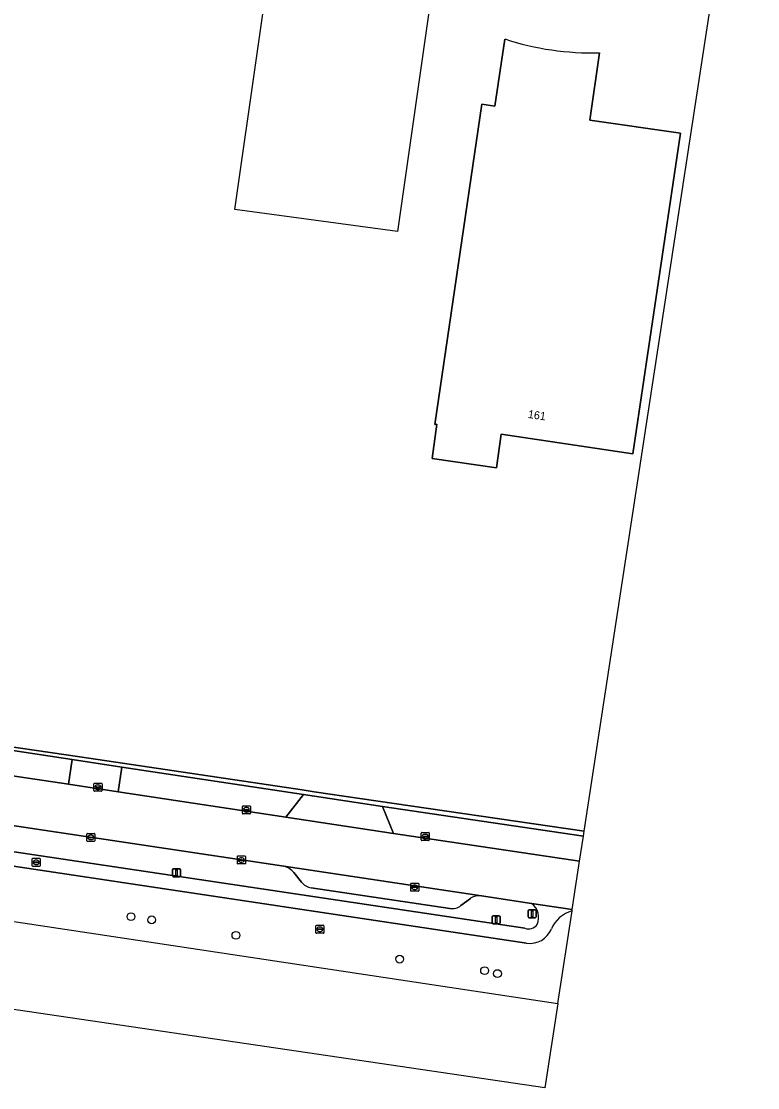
# Model space of a CAD drawing. Extents: x 163683 to 164494, y 382709 to 383872.
# Drawn here: x 164082.5 to 164174.5, y 382708.7 to 382841.9 of the extents above; entities that cross this region are included whole.
import ezdxf

# ---------------------------------------------------------------- set-up
doc = ezdxf.new("R2010")
doc.units = 0
for name, color, linetype in [('IMGEO_Berm_groen', 7, 'Continuous'), ('IMGEO_Boom', 7, 'Continuous'), ('IMGEO_Erf', 7, 'Continuous'), ('IMGEO_Fietspad_open', 7, 'Continuous'), ('IMGEO_Groenvoorziening', 7, 'Continuous'), ('IMGEO_Kolk', 7, 'Continuous'), ('IMGEO_Lichtmast', 7, 'Continuous'), ('IMGEO_Pand', 7, 'Continuous'), ('IMGEO_Pand_nummerreeks', 7, 'Continuous'), ('IMGEO_Pand_vergunning_verleend', 7, 'Continuous'), ('IMGEO_Parkeervlak_open', 7, 'Continuous'), ('IMGEO_Rijbaan_lokaal_open', 7, 'Continuous'), ('IMGEO_Rioolput', 7, 'Continuous'), ('IMGEO_Verkeersbordpaal', 7, 'Continuous'), ('IMGEO_Voetpad_open', 7, 'Continuous'), ('IMGEO_Waterloop', 7, 'Continuous')]:
    doc.layers.add(name, color=color, linetype=linetype)

msp = doc.modelspace()

# ---------------------------------------------------------------- linework, layer by layer
at = {"layer": 'IMGEO_Berm_groen'}
for points in [[(164025.95, 382749.73), (164025.49, 382746.53), (164145.37, 382728.61)], [(164115.25, 382736.34), (164025.95, 382749.73)], [(164117.47, 382734.35), (164116.5, 382735.56)], [(164136.02, 382731.08), (164118.7, 382733.66)], [(164138.61, 382732.34), (164137.39, 382731.46)], [(164146.24, 382731.7), (164139.98, 382732.64)]]:
    msp.add_lwpolyline(points, dxfattribs=at)
for centre, radius, start, end in [((164114.87, 382734.32), 2.05, 37.0321, 79.2448), ((164119.08, 382735.77), 2.15, 221.1897, 259.7116), ((164139.7, 382730.61), 2.05, 82.0143, 122.0036), ((164144.94, 382729.94), 2.18, 336.7961, 53.432), ((164136.34, 382732.62), 1.57, 258.5109, 312.0207), ((164145.85, 382729.86), 1.34, 249.196, 324.4701)]:
    msp.add_arc(centre, radius, start, end, dxfattribs=at)
at = {"layer": 'IMGEO_Boom'}
for centre in [(164096.16, 382730.05), (164098.75, 382729.65), (164109.28, 382727.72), (164129.75, 382724.75), (164140.36, 382723.31), (164141.97, 382722.94)]:
    msp.add_circle(centre, 0.489, dxfattribs=at)
at = {"layer": 'IMGEO_Erf'}
for points in [[(164076.6, 382751.95), (164089.76, 382750), (164117.54, 382745.89), (164119.07, 382745.66), (164124.77, 382744.83), (164152.81, 382740.72), (164172.2, 382867.23), (164171.72, 382867.3), (164174.49, 382886.26), (164165.52, 382887.66), (164165.46, 382887.29), (164147.17, 382890.23), (164146.96, 382890.27), (164142.09, 382891.05), (164141.8, 382889.15), (164141.95, 382889.13), (164141.39, 382885.06), (164138.4, 382885.49), (164138.99, 382889.54), (164139.16, 382889.51), (164139.68, 382892.92), (164090.55, 382900.02), (164089.55, 382900.17), (164080.01, 382901.54)], [(164154.71, 382837.95), (164153.53, 382829.54), (164164.83, 382827.91), (164158.9, 382787.87), (164142.42, 382790.3), (164141.84, 382786.12), (164133.8, 382787.27), (164134.41, 382791.55), (164134.14, 382791.52), (164140.03, 382831.52), (164141.65, 382831.28), (164142.88, 382839.68)]]:
    msp.add_lwpolyline(points, dxfattribs=at)
msp.add_arc((164153.84, 382873.25), 35.31, 251.9184, 271.4148, dxfattribs=at)
at = {"layer": 'IMGEO_Fietspad_open'}
for points in [[(164145.37, 382728.61), (164025.49, 382746.53), (164025.95, 382749.73), (164024.22, 382749.98), (164023.68, 382746.79), (163989.35, 382751.87), (163943.93, 382758.59), (163798.25, 382780.16), (163792.5, 382781.01), (163764.15, 382785.23), (163700.86, 382794.64), (163698.7, 382794.97), (163698.46, 382793.12), (163700.77, 382792.77), (163796.75, 382778.55), (163938.7, 382757.53), (163989.01, 382750.08), (164063.39, 382739.07), (164145.61, 382726.74)], [(164151.31, 382730.94), (164146.24, 382731.7)], [(164151.29, 382730.77), (164151.31, 382730.94)]]:
    msp.add_lwpolyline(points, dxfattribs=at)
for centre, radius, start, end in [((164144.94, 382729.94), 2.18, 336.7961, 53.432), ((164152.36, 382726.95), 3.97, 105.708, 156.7954), ((164145.85, 382729.86), 1.34, 249.196, 324.4701), ((164146.02, 382729.63), 2.92, 261.8889, 337.4259)]:
    msp.add_arc(centre, radius, start, end, dxfattribs=at)
at = {"layer": 'IMGEO_Groenvoorziening'}
for points in [[(164145.61, 382726.74), (164063.39, 382739.07), (163989.01, 382750.08), (163938.7, 382757.53), (163937.74, 382750.94), (163944.09, 382750), (163987.79, 382743.54), (164000, 382741.74), (164149.52, 382719.2)], [(164149.52, 382719.2), (164151.29, 382730.77)]]:
    msp.add_lwpolyline(points, dxfattribs=at)
for centre, radius, start, end in [((164152.36, 382726.95), 3.97, 105.708, 156.7954), ((164146.02, 382729.63), 2.92, 261.8889, 337.4259)]:
    msp.add_arc(centre, radius, start, end, dxfattribs=at)
at = {"layer": 'IMGEO_Kolk'}
for p, q in [((164091.53, 382745.8), (164091.53, 382746.65)), ((164091.61, 382746.73), (164092.46, 382746.73)), ((164091.79, 382746.22), (164091.79, 382746.23)), ((164092.23, 382746.18), (164091.83, 382746.18)), ((164091.84, 382746.27), (164092.23, 382746.27)), ((164092.02, 382746.5), (164092.05, 382746.5)), ((164092.28, 382746.23), (164092.28, 382746.22)), ((164092.54, 382746.65), (164092.54, 382745.8)), ((164092.46, 382745.72), (164091.61, 382745.72)), ((164092.04, 382745.95), (164092.02, 382745.95)), ((164110.09, 382742.97), (164110.09, 382743.83)), ((164110.16, 382743.9), (164111.02, 382743.9)), ((164110.58, 382743.68), (164110.6, 382743.68)), ((164111.09, 382743.83), (164111.09, 382742.97)), ((164111.02, 382742.9), (164110.16, 382742.9)), ((164110.35, 382743.39), (164110.35, 382743.41)), ((164110.39, 382743.44), (164110.79, 382743.44)), ((164110.79, 382743.36), (164110.39, 382743.36)), ((164110.6, 382743.12), (164110.58, 382743.12)), ((164110.83, 382743.41), (164110.83, 382743.39)), ((164090.64, 382739.52), (164090.64, 382740.37)), ((164090.71, 382740.45), (164091.57, 382740.45)), ((164090.9, 382739.94), (164090.9, 382739.95)), ((164090.94, 382739.99), (164091.34, 382739.99)), ((164091.34, 382739.9), (164090.94, 382739.9)), ((164091.15, 382739.67), (164091.12, 382739.67)), ((164091.13, 382740.23), (164091.15, 382740.23)), ((164091.38, 382739.95), (164091.38, 382739.94)), ((164091.64, 382740.37), (164091.64, 382739.52)), ((164132.44, 382739.63), (164132.44, 382740.49)), ((164132.52, 382740.56), (164133.37, 382740.56)), ((164133.37, 382739.56), (164132.52, 382739.56)), ((164132.7, 382740.05), (164132.7, 382740.07)), ((164133.14, 382740.02), (164132.74, 382740.02)), ((164132.75, 382740.1), (164133.14, 382740.1)), ((164132.93, 382740.34), (164132.96, 382740.34)), ((164132.95, 382739.78), (164132.93, 382739.78)), ((164133.19, 382740.07), (164133.19, 382740.05)), ((164133.44, 382740.49), (164133.44, 382739.63)), ((164091.57, 382739.45), (164090.71, 382739.45)), ((164109.46, 382736.7), (164109.46, 382737.55)), ((164109.53, 382737.63), (164110.39, 382737.63)), ((164109.72, 382737.12), (164109.72, 382737.13)), ((164109.76, 382737.17), (164110.16, 382737.17)), ((164110.15, 382737.08), (164109.76, 382737.08)), ((164109.97, 382736.85), (164109.94, 382736.85)), ((164109.95, 382737.41), (164109.97, 382737.41)), ((164110.2, 382737.13), (164110.2, 382737.12)), ((164110.46, 382737.55), (164110.46, 382736.7)), ((164110.39, 382736.63), (164109.53, 382736.63)), ((164131.13, 382733.29), (164131.13, 382734.15)), ((164131.2, 382734.22), (164132.05, 382734.22)), ((164132.13, 382734.15), (164132.13, 382733.29)), ((164132.05, 382733.22), (164131.2, 382733.22)), ((164131.38, 382733.71), (164131.38, 382733.73)), ((164131.82, 382733.68), (164131.42, 382733.68)), ((164131.43, 382733.76), (164131.82, 382733.76)), ((164131.61, 382734), (164131.64, 382734)), ((164131.64, 382733.44), (164131.61, 382733.44)), ((164131.87, 382733.73), (164131.87, 382733.71))]:
    msp.add_line(p, q, dxfattribs=at)
for points in [[(164091.53, 382745.8), (164091.53, 382746.65)], [(164091.61, 382746.73), (164092.46, 382746.73)], [(164092.54, 382746.65), (164092.54, 382745.8)], [(164092.46, 382745.72), (164091.61, 382745.72)], [(164110.09, 382742.97), (164110.09, 382743.83)], [(164110.16, 382743.9), (164111.02, 382743.9)], [(164111.09, 382743.83), (164111.09, 382742.97)], [(164111.02, 382742.9), (164110.16, 382742.9)], [(164090.64, 382739.52), (164090.64, 382740.37)], [(164090.71, 382740.45), (164091.57, 382740.45)], [(164091.64, 382740.37), (164091.64, 382739.52)], [(164132.44, 382739.63), (164132.44, 382740.49)], [(164132.52, 382740.56), (164133.37, 382740.56)], [(164133.37, 382739.56), (164132.52, 382739.56)], [(164133.44, 382740.49), (164133.44, 382739.63)], [(164091.57, 382739.45), (164090.71, 382739.45)], [(164109.46, 382736.7), (164109.46, 382737.55)], [(164109.53, 382737.63), (164110.39, 382737.63)], [(164110.46, 382737.55), (164110.46, 382736.7)], [(164110.39, 382736.63), (164109.53, 382736.63)], [(164131.13, 382733.29), (164131.13, 382734.15)], [(164131.2, 382734.22), (164132.05, 382734.22)], [(164132.13, 382734.15), (164132.13, 382733.29)], [(164132.05, 382733.22), (164131.2, 382733.22)]]:
    msp.add_lwpolyline(points, dxfattribs=at)
for centre, radius, start, end in [((164091.61, 382746.65), 0.0765, 91.552, 178.448), ((164091.61, 382746.65), 0.0765, 91.552, 178.448), ((164091.83, 382746.23), 0.0403, 85.8775, 175.7526), ((164091.83, 382746.22), 0.0366, 178.938, 274.7102), ((164092.24, 382746.23), 0.0386, 1.7309, 96.639), ((164092.23, 382746.22), 0.043, 264.8664, 352.4533), ((164092.46, 382746.65), 0.0765, 1.552, 88.448), ((164092.46, 382746.65), 0.0765, 1.552, 88.448), ((164091.61, 382745.8), 0.0765, 181.552, 268.448), ((164091.61, 382745.8), 0.0765, 181.552, 268.448), ((164092.46, 382745.8), 0.0765, 271.552, 358.448), ((164092.46, 382745.8), 0.0765, 271.552, 358.448), ((164110.17, 382743.82), 0.0765, 91.552, 178.448), ((164110.17, 382743.82), 0.0765, 91.552, 178.448), ((164111.01, 382743.82), 0.0765, 1.552, 88.448), ((164111.01, 382743.82), 0.0765, 1.552, 88.448), ((164110.17, 382742.97), 0.0765, 181.552, 268.448), ((164110.17, 382742.97), 0.0765, 181.552, 268.448), ((164110.39, 382743.4), 0.0403, 85.8775, 175.7526), ((164110.39, 382743.39), 0.0366, 178.938, 274.7102), ((164110.79, 382743.4), 0.0386, 1.7309, 96.639), ((164110.79, 382743.4), 0.043, 264.8664, 352.4533), ((164111.01, 382742.97), 0.0765, 271.552, 358.448), ((164111.01, 382742.97), 0.0765, 271.552, 358.448), ((164090.72, 382740.37), 0.0765, 91.552, 178.448), ((164090.72, 382740.37), 0.0765, 91.552, 178.448), ((164090.72, 382739.52), 0.0765, 181.552, 268.448), ((164090.72, 382739.52), 0.0765, 181.552, 268.448), ((164090.94, 382739.95), 0.0403, 85.8775, 175.7526), ((164090.93, 382739.94), 0.0366, 178.938, 274.7102), ((164091.34, 382739.95), 0.0386, 1.7309, 96.639), ((164091.34, 382739.95), 0.043, 264.8664, 352.4533), ((164091.56, 382740.37), 0.0765, 1.552, 88.448), ((164091.56, 382740.37), 0.0765, 1.552, 88.448), ((164091.56, 382739.52), 0.0765, 271.552, 358.448), ((164091.56, 382739.52), 0.0765, 271.552, 358.448), ((164132.52, 382740.49), 0.0765, 91.552, 178.448), ((164132.52, 382740.49), 0.0765, 91.552, 178.448), ((164132.52, 382739.64), 0.0765, 181.552, 268.448), ((164132.52, 382739.64), 0.0765, 181.552, 268.448), ((164132.74, 382740.06), 0.0403, 85.8775, 175.7526), ((164132.74, 382740.05), 0.0366, 178.938, 274.7102), ((164133.15, 382740.07), 0.0386, 1.7309, 96.639), ((164133.14, 382740.06), 0.043, 264.8664, 352.4533), ((164133.37, 382740.49), 0.0765, 1.552, 88.448), ((164133.37, 382740.49), 0.0765, 1.552, 88.448), ((164133.37, 382739.64), 0.0765, 271.552, 358.448), ((164133.37, 382739.64), 0.0765, 271.552, 358.448), ((164109.53, 382737.55), 0.0765, 91.552, 178.448), ((164109.53, 382737.55), 0.0765, 91.552, 178.448), ((164109.76, 382737.13), 0.0403, 85.8775, 175.7526), ((164109.75, 382737.12), 0.0366, 178.938, 274.7102), ((164110.16, 382737.13), 0.043, 264.8664, 352.4533), ((164110.16, 382737.13), 0.0386, 1.7309, 96.639), ((164110.38, 382737.55), 0.0765, 1.552, 88.448), ((164110.38, 382737.55), 0.0765, 1.552, 88.448), ((164109.53, 382736.7), 0.0765, 181.552, 268.448), ((164109.53, 382736.7), 0.0765, 181.552, 268.448), ((164110.38, 382736.7), 0.0765, 271.552, 358.448), ((164110.38, 382736.7), 0.0765, 271.552, 358.448), ((164131.2, 382734.14), 0.0765, 91.552, 178.448), ((164131.2, 382734.14), 0.0765, 91.552, 178.448), ((164132.05, 382734.14), 0.0765, 1.552, 88.448), ((164132.05, 382734.14), 0.0765, 1.552, 88.448), ((164131.2, 382733.29), 0.0765, 181.552, 268.448), ((164131.2, 382733.29), 0.0765, 181.552, 268.448), ((164131.42, 382733.72), 0.0403, 85.8775, 175.7526), ((164131.42, 382733.71), 0.0366, 178.938, 274.7102), ((164131.83, 382733.72), 0.0386, 1.7309, 96.639), ((164131.83, 382733.72), 0.043, 264.8664, 352.4533), ((164132.05, 382733.29), 0.0765, 271.552, 358.448), ((164132.05, 382733.29), 0.0765, 271.552, 358.448)]:
    msp.add_arc(centre, radius, start, end, dxfattribs=at)
for centre, major_axis, ratio, start_param, end_param in [((164092.02, 382746.22), (-0.387, 0.002), 0.722429, 4.712389, 7.853982), ((164092.05, 382746.22), (-0.39, 0.002), 0.717154, 1.570796, 4.712389), ((164110.58, 382743.4), (-0.387, 0.002), 0.722429, 4.712389, 7.853982), ((164110.6, 382743.4), (-0.39, 0.002), 0.717154, 1.570796, 4.712389), ((164091.13, 382739.95), (-0.387, 0.002), 0.722429, 4.712389, 7.853982), ((164091.15, 382739.95), (-0.39, 0.002), 0.717154, 1.570796, 4.712389), ((164132.93, 382740.06), (-0.387, 0.002), 0.722429, 4.712389, 7.853982), ((164132.95, 382740.06), (-0.39, 0.002), 0.717154, 1.570796, 4.712389), ((164109.95, 382737.13), (-0.387, 0.002), 0.722429, 4.712389, 7.853982), ((164109.97, 382737.13), (-0.39, 0.002), 0.717154, 1.570796, 4.712389), ((164131.61, 382733.72), (-0.387, 0.002), 0.722429, 4.712389, 7.853982), ((164131.64, 382733.72), (-0.39, 0.002), 0.717154, 1.570796, 4.712389)]:
    msp.add_ellipse(centre, major_axis=major_axis, ratio=ratio, start_param=start_param, end_param=end_param, dxfattribs=at)
at = {"layer": 'IMGEO_Lichtmast'}
for p, q in [((164101.35, 382735.14), (164101.35, 382735.94)), ((164101.35, 382735.94), (164101.35, 382735.14)), ((164101.45, 382736.04), (164102.24, 382736.04)), ((164102.24, 382736.04), (164101.45, 382736.04)), ((164102.34, 382735.94), (164102.34, 382735.14)), ((164102.34, 382735.14), (164102.34, 382735.94)), ((164102.24, 382735.04), (164101.45, 382735.04)), ((164101.45, 382735.04), (164102.24, 382735.04)), ((164141.4, 382730.16), (164142.19, 382730.16)), ((164142.19, 382730.16), (164141.4, 382730.16)), ((164141.3, 382729.26), (164141.3, 382730.06)), ((164141.3, 382730.06), (164141.3, 382729.26)), ((164142.19, 382729.16), (164141.4, 382729.16)), ((164141.4, 382729.16), (164142.19, 382729.16)), ((164142.29, 382730.06), (164142.29, 382729.26)), ((164142.29, 382729.26), (164142.29, 382730.06))]:
    msp.add_line(p, q, dxfattribs=at)
for points in [[(164101.77, 382735.92), (164101.92, 382735.92), (164101.92, 382735.17), (164101.77, 382735.17), (164101.77, 382735.92)], [(164141.72, 382730.04), (164141.87, 382730.04), (164141.87, 382729.29), (164141.72, 382729.29), (164141.72, 382730.04)]]:
    msp.add_lwpolyline(points, dxfattribs=at)
for centre, start, end in [((164101.45, 382735.94), 90, 180), ((164101.45, 382735.94), 90, 180), ((164102.24, 382735.94), 0, 90), ((164102.24, 382735.94), 360, 90), ((164101.45, 382735.14), 180, 270), ((164101.45, 382735.14), 180, 270), ((164102.24, 382735.14), 270, 0), ((164102.24, 382735.14), 270, 0), ((164141.4, 382730.06), 90, 180), ((164141.4, 382730.06), 90, 180), ((164142.19, 382730.06), 0, 90), ((164142.19, 382730.06), 360, 90), ((164141.4, 382729.26), 180, 270), ((164141.4, 382729.26), 180, 270), ((164142.19, 382729.26), 270, 0), ((164142.19, 382729.26), 270, 0)]:
    msp.add_arc(centre, 0.1, start, end, dxfattribs=at)
at = {"layer": 'IMGEO_Pand'}
msp.add_lwpolyline([(164142.88, 382839.68), (164141.65, 382831.28), (164140.03, 382831.52), (164134.14, 382791.52), (164134.41, 382791.55), (164133.8, 382787.27), (164141.84, 382786.12), (164142.42, 382790.3), (164158.9, 382787.87), (164164.83, 382827.91), (164153.53, 382829.54), (164154.71, 382837.95)], dxfattribs=at)
msp.add_arc((164153.84, 382873.25), 35.31, 251.9184, 271.4148, dxfattribs=at)
at = {"layer": 'IMGEO_Pand_vergunning_verleend'}
msp.add_lwpolyline([(164109.15, 382818.39), (164117.67, 382878.05), (164116.07, 382878.27), (164117.6, 382888.99), (164133.91, 382886.66), (164133.8, 382885.84), (164139.37, 382885.05), (164129.46, 382815.63)], close=True, dxfattribs=at)
at = {"layer": 'IMGEO_Parkeervlak_open'}
for points in [[(164062.8, 382750.4), (164088.36, 382746.61), (164088.83, 382749.68), (164063.23, 382753.54)], [(164094.55, 382745.64), (164115.5, 382742.49), (164117.73, 382745.3), (164095.02, 382748.74)], [(164152.24, 382736.97), (164152.72, 382740.12), (164127.62, 382743.8), (164128.99, 382740.45)]]:
    msp.add_lwpolyline(points, close=True, dxfattribs=at)
for points in [[(164139.98, 382732.64), (164115.25, 382736.34)], [(164116.5, 382735.56), (164117.47, 382734.35)], [(164118.7, 382733.66), (164136.02, 382731.08)], [(164137.39, 382731.46), (164138.61, 382732.34)]]:
    msp.add_lwpolyline(points, dxfattribs=at)
for centre, radius, start, end in [((164114.87, 382734.32), 2.05, 37.0321, 79.2448), ((164119.08, 382735.77), 2.15, 221.1897, 259.7116), ((164139.7, 382730.61), 2.05, 82.0143, 122.0036), ((164136.34, 382732.62), 1.57, 258.5109, 312.0207)]:
    msp.add_arc(centre, radius, start, end, dxfattribs=at)
at = {"layer": 'IMGEO_Rijbaan_lokaal_open'}
msp.add_lwpolyline([(163896.6, 382768.79), (163989.94, 382755.04), (164024.22, 382749.98), (164025.95, 382749.73), (164115.25, 382736.34), (164139.98, 382732.64), (164146.24, 382731.7), (164151.31, 382730.94), (164152.24, 382736.97), (164128.99, 382740.45), (164115.5, 382742.49), (164094.55, 382745.64), (164088.36, 382746.61), (164062.8, 382750.4), (164055.63, 382751.5), (164032.24, 382754.97), (164024.78, 382756.1), (164003.68, 382759.2), (163991.69, 382760.99), (163974.68, 382763.48)], dxfattribs=at)
at = {"layer": 'IMGEO_Rioolput'}
for p, q in [((164083.81, 382736.41), (164083.81, 382737.26)), ((164083.88, 382737.34), (164084.74, 382737.34)), ((164084.07, 382736.83), (164084.07, 382736.84)), ((164084.11, 382736.88), (164084.51, 382736.88)), ((164084.51, 382736.79), (164084.11, 382736.79)), ((164084.3, 382737.11), (164084.32, 382737.11)), ((164084.55, 382736.84), (164084.55, 382736.83)), ((164084.81, 382737.26), (164084.81, 382736.41)), ((164084.74, 382736.33), (164083.88, 382736.33)), ((164084.32, 382736.56), (164084.3, 382736.56)), ((164119.27, 382728.05), (164119.27, 382728.9)), ((164119.35, 382728.98), (164120.2, 382728.98)), ((164120.27, 382728.9), (164120.27, 382728.05)), ((164120.2, 382727.98), (164119.35, 382727.98)), ((164119.53, 382728.47), (164119.53, 382728.48)), ((164119.97, 382728.43), (164119.57, 382728.43)), ((164119.58, 382728.52), (164119.97, 382728.52)), ((164119.76, 382728.76), (164119.79, 382728.76)), ((164119.78, 382728.2), (164119.76, 382728.2)), ((164120.02, 382728.48), (164120.02, 382728.47))]:
    msp.add_line(p, q, dxfattribs=at)
for points in [[(164083.81, 382736.41), (164083.81, 382737.26)], [(164083.88, 382737.34), (164084.74, 382737.34)], [(164084.81, 382737.26), (164084.81, 382736.41)], [(164084.74, 382736.33), (164083.88, 382736.33)], [(164119.27, 382728.05), (164119.27, 382728.9)], [(164119.35, 382728.98), (164120.2, 382728.98)], [(164120.27, 382728.9), (164120.27, 382728.05)], [(164120.2, 382727.98), (164119.35, 382727.98)]]:
    msp.add_lwpolyline(points, dxfattribs=at)
for centre, radius, start, end in [((164083.89, 382737.26), 0.0765, 91.552, 178.448), ((164083.89, 382737.26), 0.0765, 91.552, 178.448), ((164084.11, 382736.84), 0.0403, 85.8775, 175.7526), ((164084.11, 382736.83), 0.0366, 178.938, 274.7102), ((164084.51, 382736.84), 0.0386, 1.7309, 96.639), ((164084.51, 382736.83), 0.043, 264.8664, 352.4533), ((164084.73, 382737.26), 0.0765, 1.552, 88.448), ((164084.73, 382737.26), 0.0765, 1.552, 88.448), ((164083.89, 382736.41), 0.0765, 181.552, 268.448), ((164083.89, 382736.41), 0.0765, 181.552, 268.448), ((164084.73, 382736.41), 0.0765, 271.552, 358.448), ((164084.73, 382736.41), 0.0765, 271.552, 358.448), ((164119.35, 382728.9), 0.0765, 91.552, 178.448), ((164119.35, 382728.9), 0.0765, 91.552, 178.448), ((164120.2, 382728.9), 0.0765, 1.552, 88.448), ((164120.2, 382728.9), 0.0765, 1.552, 88.448), ((164119.35, 382728.05), 0.0765, 181.552, 268.448), ((164119.35, 382728.05), 0.0765, 181.552, 268.448), ((164119.57, 382728.48), 0.0403, 85.8775, 175.7526), ((164119.57, 382728.47), 0.0366, 178.938, 274.7102), ((164119.98, 382728.48), 0.0386, 1.7309, 96.639), ((164119.97, 382728.48), 0.043, 264.8664, 352.4533), ((164120.2, 382728.05), 0.0765, 271.552, 358.448), ((164120.2, 382728.05), 0.0765, 271.552, 358.448)]:
    msp.add_arc(centre, radius, start, end, dxfattribs=at)
for centre, major_axis, ratio, start_param, end_param in [((164084.3, 382736.83), (-0.387, 0.002), 0.722429, 4.712389, 7.853982), ((164084.32, 382736.83), (-0.39, 0.002), 0.717154, 1.570796, 4.712389), ((164119.76, 382728.48), (-0.387, 0.002), 0.722429, 4.712389, 7.853982), ((164119.78, 382728.48), (-0.39, 0.002), 0.717154, 1.570796, 4.712389)]:
    msp.add_ellipse(centre, major_axis=major_axis, ratio=ratio, start_param=start_param, end_param=end_param, dxfattribs=at)
at = {"layer": 'IMGEO_Verkeersbordpaal'}
for p, q in [((164145.81, 382730.01), (164145.81, 382730.81)), ((164145.81, 382730.81), (164145.81, 382730.01)), ((164145.91, 382730.91), (164146.7, 382730.91)), ((164146.7, 382730.91), (164145.91, 382730.91)), ((164146.8, 382730.81), (164146.8, 382730.01)), ((164146.8, 382730.01), (164146.8, 382730.81)), ((164146.7, 382729.91), (164145.91, 382729.91)), ((164145.91, 382729.91), (164146.7, 382729.91))]:
    msp.add_line(p, q, dxfattribs=at)
msp.add_lwpolyline([(164146.23, 382730.78), (164146.38, 382730.78), (164146.38, 382730.03), (164146.23, 382730.03), (164146.23, 382730.78)], dxfattribs=at)
for centre, start, end in [((164145.91, 382730.81), 90, 180), ((164145.91, 382730.81), 90, 180), ((164146.7, 382730.81), 0, 90), ((164146.7, 382730.81), 360, 90), ((164145.91, 382730.01), 180, 270), ((164145.91, 382730.01), 180, 270), ((164146.7, 382730.01), 270, 0), ((164146.7, 382730.01), 270, 0)]:
    msp.add_arc(centre, 0.1, start, end, dxfattribs=at)
at = {"layer": 'IMGEO_Voetpad_open'}
for points in [[(164152.81, 382740.72), (164124.77, 382744.83), (164119.07, 382745.66), (164117.54, 382745.89), (164089.76, 382750), (164076.6, 382751.95), (164065.05, 382753.69), (164065.06, 382753.76), (164064.7, 382753.81), (164034.85, 382758.2), (164034.79, 382757.8), (164056.1, 382754.62), (164063.23, 382753.54), (164088.83, 382749.68), (164095.02, 382748.74), (164117.73, 382745.3), (164127.62, 382743.8), (164152.72, 382740.12)], [(164088.83, 382749.68), (164088.36, 382746.61), (164094.55, 382745.64), (164095.02, 382748.74)], [(164117.73, 382745.3), (164115.5, 382742.49), (164128.99, 382740.45), (164127.62, 382743.8)]]:
    msp.add_lwpolyline(points, close=True, dxfattribs=at)
at = {"layer": 'IMGEO_Waterloop'}
msp.add_lwpolyline([(164149.52, 382719.2), (164147.9, 382708.69), (163683.11, 382777.18), (163685.61, 382793.19), (163698.23, 382791.35), (163795.71, 382777.07), (163909.13, 382760.46), (163937.69, 382750.61), (163937.74, 382750.94), (163944.09, 382750), (163987.79, 382743.54), (164000, 382741.74), (164149.52, 382719.2)], dxfattribs=at)

# ---------------------------------------------------------------- texts
at = {"layer": 'IMGEO_Pand_nummerreeks'}
msp.add_text('161', height=1, rotation=351.6019, dxfattribs=at).set_placement((164145.73, 382792.36))

doc.saveas('drawing.dxf')
